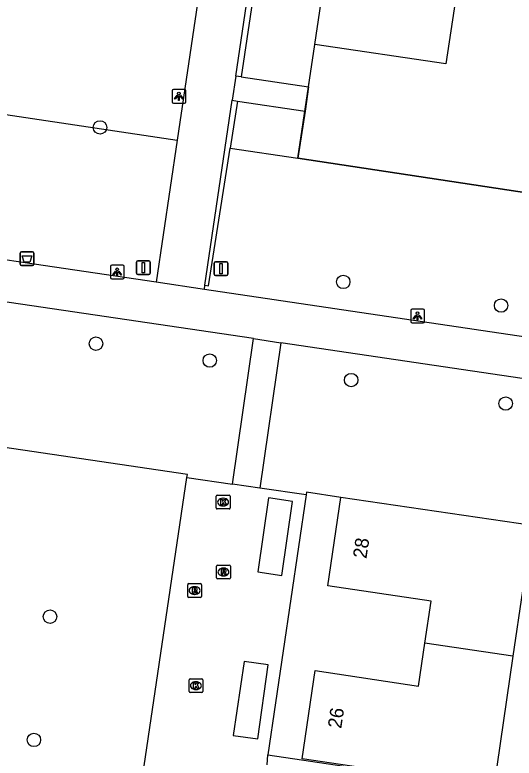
# Model space of a CAD drawing. Extents: x 164150 to 165261, y 382513 to 383432.
# Drawn here: x 164477.9 to 164514.2, y 382999.8 to 383053.9 of the extents above; entities that cross this region are included whole.
import ezdxf

# ---------------------------------------------------------------- set-up
doc = ezdxf.new("R2010")
doc.units = 0
for name, color, linetype in [('IMGEO_Afvalbak', 7, 'Continuous'), ('IMGEO_Boom', 7, 'Continuous'), ('IMGEO_Fietspad_gesloten', 7, 'Continuous'), ('IMGEO_Groenvoorziening', 7, 'Continuous'), ('IMGEO_Haag', 7, 'Continuous'), ('IMGEO_Hek', 7, 'Continuous'), ('IMGEO_Kolk', 7, 'Continuous'), ('IMGEO_Lichtpunt', 7, 'Continuous'), ('IMGEO_Pand', 7, 'Continuous'), ('IMGEO_Pand_nummerreeks', 7, 'Continuous'), ('IMGEO_Rijbaan_lokaal_open', 7, 'Continuous'), ('IMGEO_Rioolput', 7, 'Continuous'), ('IMGEO_Verkeersbordpaal', 7, 'Continuous'), ('IMGEO_Voetpad_gesloten', 7, 'Continuous'), ('IMGEO_Voetpad_halfverhard', 7, 'Continuous'), ('IMGEO_Voetpad_open', 7, 'Continuous')]:
    doc.layers.add(name, color=color, linetype=linetype)

msp = doc.modelspace()

# ---------------------------------------------------------------- linework, layer by layer
at = {"layer": 'IMGEO_Afvalbak'}
for p, q in [((164478.364, 383036.636), (164479.154, 383036.636)), ((164479.154, 383036.636), (164478.364, 383036.636)), ((164478.264, 383035.736), (164478.264, 383036.536)), ((164478.264, 383036.536), (164478.264, 383035.736)), ((164479.254, 383036.536), (164479.254, 383035.736)), ((164479.254, 383035.736), (164479.254, 383036.536)), ((164479.154, 383035.636), (164478.364, 383035.636)), ((164478.364, 383035.636), (164479.154, 383035.636))]:
    msp.add_line(p, q, dxfattribs=at)
msp.add_lwpolyline([(164478.407, 383036.35), (164479.111, 383036.35), (164478.962, 383035.88), (164478.556, 383035.88), (164478.407, 383036.35)], dxfattribs=at)
for centre, start, end in [((164478.364, 383036.536), 90, 180), ((164478.364, 383036.536), 90, 180), ((164479.154, 383036.536), 0, 90), ((164479.154, 383036.536), 360, 90), ((164478.364, 383035.736), 180, 270), ((164478.364, 383035.736), 180, 270), ((164479.154, 383035.736), 270, 0), ((164479.154, 383035.736), 270, 0)]:
    msp.add_arc(centre, 0.1, start, end, dxfattribs=at)
at = {"layer": 'IMGEO_Boom'}
for centre in [(164484.075, 383045.692), (164501.769, 383034.443), (164513.25, 383032.723), (164483.78, 383029.945), (164492.055, 383028.719), (164502.343, 383027.299), (164513.585, 383025.587), (164480.437, 383010.074), (164479.266, 383001.1)]:
    msp.add_circle(centre, 0.489, dxfattribs=at)
at = {"layer": 'IMGEO_Fietspad_gesloten'}
for points in [[(164488.159, 383034.419), (164477.812, 383035.957), (164476.86, 383036.098), (164470.165, 383037.076)], [(164495.251, 383030.312), (164475.967, 383033.169), (164468.317, 383034.298)], [(164491.665, 383033.898), (164488.159, 383034.419)], [(164540.385, 383026.655), (164491.665, 383033.898)], [(164493.71, 383019.713), (164495.251, 383030.312)], [(164495.251, 383030.312), (164497.229, 383030.019)], [(164497.229, 383030.019), (164495.689, 383019.425)], [(164557.267, 383021.125), (164497.229, 383030.019)]]:
    msp.add_lwpolyline(points, dxfattribs=at)
at = {"layer": 'IMGEO_Groenvoorziening'}
for points in [[(164499.25, 383048.639), (164499.711, 383051.727)], [(164471.706, 383047.448), (164489.692, 383044.763)], [(164498.987, 383046.877), (164498.474, 383043.442)], [(164493.537, 383044.188), (164498.474, 383043.442)], [(164498.474, 383043.442), (164537.669, 383037.513), (164537.713, 383037.811)], [(164490.395, 383020.195), (164490.427, 383020.412), (164473.524, 383022.914)], [(164501.59, 383018.76), (164499.092, 383019.13), (164499.063, 383018.935)]]:
    msp.add_lwpolyline(points, dxfattribs=at)
at = {"layer": 'IMGEO_Haag'}
for points in [[(164497.85, 383072.978), (164494.335, 383049.373)], [(164494.073, 383047.611), (164493.537, 383044.188)], [(164491.71, 383034.202), (164491.967, 383034.165), (164493.537, 383044.188)]]:
    msp.add_lwpolyline(points, dxfattribs=at)
at = {"layer": 'IMGEO_Hek'}
for points in [[(164498.474, 383043.442), (164499.711, 383051.727)], [(164537.713, 383037.811), (164537.669, 383037.513), (164498.474, 383043.442)]]:
    msp.add_lwpolyline(points, dxfattribs=at)
at = {"layer": 'IMGEO_Kolk'}
for p, q in [((164492.531, 383017.986), (164492.531, 383018.838)), ((164492.606, 383018.912), (164493.458, 383018.912)), ((164493.532, 383018.838), (164493.532, 383017.986)), ((164493.019, 383018.692), (164493.044, 383018.692)), ((164493.458, 383017.912), (164492.606, 383017.912)), ((164493.042, 383018.132), (164493.017, 383018.132)), ((164490.552, 383004.625), (164490.552, 383005.477)), ((164490.627, 383005.551), (164491.479, 383005.551)), ((164491.04, 383005.331), (164491.065, 383005.331)), ((164491.553, 383005.477), (164491.553, 383004.625)), ((164491.063, 383004.771), (164491.038, 383004.771)), ((164491.479, 383004.551), (164490.627, 383004.551))]:
    msp.add_line(p, q, dxfattribs=at)
for points in [[(164492.531, 383017.986), (164492.531, 383018.838)], [(164492.606, 383018.912), (164493.458, 383018.912)], [(164493.532, 383018.838), (164493.532, 383017.986)], [(164492.852, 383018.612), (164492.975, 383018.612), (164492.975, 383018.461), (164493.105, 383018.612), (164493.269, 383018.612), (164493.123, 383018.461), (164493.276, 383018.212), (164493.124, 383018.212), (164493.039, 383018.376), (164492.975, 383018.309), (164492.975, 383018.212), (164492.852, 383018.212), (164492.852, 383018.612)], [(164493.458, 383017.912), (164492.606, 383017.912)], [(164490.552, 383004.625), (164490.552, 383005.477)], [(164490.627, 383005.551), (164491.479, 383005.551)], [(164490.873, 383005.251), (164490.996, 383005.251), (164490.996, 383005.1), (164491.126, 383005.251), (164491.29, 383005.251), (164491.144, 383005.1), (164491.297, 383004.851), (164491.145, 383004.851), (164491.06, 383005.015), (164490.996, 383004.948), (164490.996, 383004.851), (164490.873, 383004.851), (164490.873, 383005.251)], [(164491.553, 383005.477), (164491.553, 383004.625)], [(164491.479, 383004.551), (164490.627, 383004.551)]]:
    msp.add_lwpolyline(points, dxfattribs=at)
for centre, start, end in [((164492.608, 383018.836), 91.552, 178.448), ((164492.608, 383018.836), 91.552, 178.448), ((164493.456, 383018.836), 1.552, 88.448), ((164493.456, 383018.836), 1.552, 88.448), ((164492.608, 383017.988), 181.552, 268.448), ((164492.608, 383017.988), 181.552, 268.448), ((164493.456, 383017.988), 271.552, 358.448), ((164493.456, 383017.988), 271.552, 358.448), ((164490.629, 383005.475), 91.552, 178.448), ((164490.629, 383005.475), 91.552, 178.448), ((164491.477, 383005.475), 1.552, 88.448), ((164491.477, 383005.475), 1.552, 88.448), ((164490.629, 383004.627), 181.552, 268.448), ((164490.629, 383004.627), 181.552, 268.448), ((164491.477, 383004.627), 271.552, 358.448), ((164491.477, 383004.627), 271.552, 358.448)]:
    msp.add_arc(centre, 0.0765, start, end, dxfattribs=at)
for centre, major_axis, ratio, start_param, end_param in [((164493.018, 383018.412), (-0.387, 0.002), 0.722429, 4.712389, 7.853982), ((164493.043, 383018.412), (-0.39, 0.002), 0.717154, 1.570796, 4.712389), ((164491.039, 383005.051), (-0.387, 0.002), 0.722429, 4.712389, 7.853982), ((164491.064, 383005.051), (-0.39, 0.002), 0.717154, 1.570796, 4.712389)]:
    msp.add_ellipse(centre, major_axis=major_axis, ratio=ratio, start_param=start_param, end_param=end_param, dxfattribs=at)
at = {"layer": 'IMGEO_Lichtpunt'}
for p, q in [((164489.315, 383048.366), (164489.315, 383047.559)), ((164489.315, 383048.366), (164489.315, 383047.559)), ((164490.217, 383048.461), (164489.409, 383048.461)), ((164490.217, 383048.461), (164489.409, 383048.461)), ((164490.311, 383047.559), (164490.311, 383048.366)), ((164490.311, 383047.559), (164490.311, 383048.366)), ((164489.409, 383047.465), (164490.217, 383047.465)), ((164489.409, 383047.465), (164490.217, 383047.465)), ((164484.83, 383035.561), (164484.83, 383034.754)), ((164484.83, 383035.561), (164484.83, 383034.754)), ((164485.732, 383035.656), (164484.924, 383035.656)), ((164485.732, 383035.656), (164484.924, 383035.656)), ((164485.826, 383034.754), (164485.826, 383035.561)), ((164485.826, 383034.754), (164485.826, 383035.561)), ((164484.924, 383034.66), (164485.732, 383034.66)), ((164484.924, 383034.66), (164485.732, 383034.66)), ((164506.678, 383032.364), (164506.678, 383031.557)), ((164506.678, 383032.364), (164506.678, 383031.557)), ((164507.58, 383032.459), (164506.772, 383032.459)), ((164507.58, 383032.459), (164506.772, 383032.459)), ((164507.674, 383031.557), (164507.674, 383032.364)), ((164507.674, 383031.557), (164507.674, 383032.364)), ((164506.772, 383031.463), (164507.58, 383031.463)), ((164506.772, 383031.463), (164507.58, 383031.463))]:
    msp.add_line(p, q, dxfattribs=at)
for points in [[(164489.689, 383048.03), (164489.728, 383048.002), (164489.54, 383047.74), (164489.502, 383047.767), (164489.689, 383048.03)], [(164489.791, 383047.982), (164489.838, 383047.982), (164489.838, 383047.66), (164489.791, 383047.66), (164489.791, 383047.982)], [(164489.901, 383048.002), (164489.939, 383048.029), (164490.126, 383047.767), (164490.087, 383047.739), (164489.901, 383048.002)], [(164485.204, 383035.225), (164485.243, 383035.197), (164485.055, 383034.935), (164485.017, 383034.962), (164485.204, 383035.225)], [(164485.306, 383035.177), (164485.353, 383035.177), (164485.353, 383034.855), (164485.306, 383034.855), (164485.306, 383035.177)], [(164485.416, 383035.197), (164485.454, 383035.224), (164485.641, 383034.962), (164485.602, 383034.934), (164485.416, 383035.197)], [(164507.052, 383032.028), (164507.091, 383032), (164506.903, 383031.738), (164506.865, 383031.765), (164507.052, 383032.028)], [(164507.154, 383031.98), (164507.201, 383031.98), (164507.201, 383031.658), (164507.154, 383031.658), (164507.154, 383031.98)], [(164507.264, 383032), (164507.302, 383032.027), (164507.489, 383031.765), (164507.45, 383031.737), (164507.264, 383032)]]:
    msp.add_lwpolyline(points, dxfattribs=at)
for centre in [(164489.814, 383048.164), (164485.329, 383035.359), (164507.177, 383032.162)]:
    msp.add_circle(centre, 0.0994, dxfattribs=at)
for centre, start, end in [((164489.409, 383048.366), 90, 180), ((164489.409, 383048.366), 90, 180), ((164490.217, 383048.366), 0, 90), ((164490.217, 383048.366), 0, 90), ((164489.409, 383047.559), 180, 270), ((164489.409, 383047.559), 180, 270), ((164490.217, 383047.559), 270, 0), ((164490.217, 383047.559), 270, 360), ((164484.924, 383035.561), 90, 180), ((164484.924, 383035.561), 90, 180), ((164485.732, 383035.561), 0, 90), ((164485.732, 383035.561), 0, 90), ((164484.924, 383034.754), 180, 270), ((164484.924, 383034.754), 180, 270), ((164485.732, 383034.754), 270, 0), ((164485.732, 383034.754), 270, 360), ((164506.772, 383032.364), 90, 180), ((164506.772, 383032.364), 90, 180), ((164507.58, 383032.364), 0, 90), ((164507.58, 383032.364), 0, 90), ((164506.772, 383031.557), 180, 270), ((164506.772, 383031.557), 180, 270), ((164507.58, 383031.557), 270, 0), ((164507.58, 383031.557), 270, 360)]:
    msp.add_arc(centre, 0.0946, start, end, dxfattribs=at)
at = {"layer": 'IMGEO_Pand'}
for points in [[(164499.711, 383051.727), (164500.898, 383059.768)], [(164510.434, 383058.359), (164509.235, 383050.319), (164499.711, 383051.727)], [(164507.703, 383008.132), (164508.161, 383011.199), (164500.641, 383012.312), (164501.59, 383018.76)], [(164515.519, 383016.715), (164501.59, 383018.76)], [(164515.519, 383016.715), (164514.115, 383007.187)], [(164514.115, 383007.187), (164512.711, 382997.659), (164498.772, 382999.727), (164499.73, 383006.146), (164507.24, 383005.025), (164507.703, 383008.132)], [(164514.115, 383007.187), (164507.703, 383008.132)]]:
    msp.add_lwpolyline(points, dxfattribs=at)
at = {"layer": 'IMGEO_Rijbaan_lokaal_open'}
for points in [[(164486.551, 382993.124), (164486.385, 382993.149), (164490.395, 383020.195)], [(164490.395, 383020.195), (164493.71, 383019.713)], [(164495.689, 383019.425), (164493.71, 383019.713)], [(164499.063, 383018.935), (164495.689, 383019.425)], [(164499.063, 383018.935), (164496.276, 383000.022)], [(164497.294, 383013.061), (164498.073, 383018.463), (164496.335, 383018.717), (164495.543, 383013.341), (164497.294, 383013.061)], [(164495.546, 383001.168), (164496.306, 383006.561), (164494.565, 383006.812), (164493.769, 383001.425), (164495.546, 383001.168)], [(164496.241, 382999.283), (164496.276, 383000.022)]]:
    msp.add_lwpolyline(points, dxfattribs=at)
at = {"layer": 'IMGEO_Rioolput'}
for p, q in [((164492.554, 383012.898), (164492.554, 383013.75)), ((164492.629, 383013.824), (164493.481, 383013.824)), ((164493.042, 383013.604), (164493.067, 383013.604)), ((164493.555, 383013.75), (164493.555, 383012.898)), ((164493.481, 383012.824), (164492.629, 383012.824)), ((164493.065, 383013.044), (164493.04, 383013.044)), ((164490.451, 383011.55), (164490.451, 383012.402)), ((164490.526, 383012.476), (164491.378, 383012.476)), ((164490.939, 383012.256), (164490.964, 383012.256)), ((164491.452, 383012.402), (164491.452, 383011.55)), ((164491.378, 383011.476), (164490.526, 383011.476)), ((164490.962, 383011.696), (164490.937, 383011.696))]:
    msp.add_line(p, q, dxfattribs=at)
for points in [[(164492.554, 383012.898), (164492.554, 383013.75)], [(164492.629, 383013.824), (164493.481, 383013.824)], [(164493.143, 383013.522), (164492.891, 383013.524), (164492.891, 383013.124)], [(164493.069, 383013.443), (164493.015, 383013.443), (164493.015, 383013.362)], [(164493.015, 383013.362), (164493.067, 383013.362)], [(164493.555, 383013.75), (164493.555, 383012.898)], [(164493.481, 383012.824), (164492.629, 383012.824)], [(164492.891, 383013.124), (164493.015, 383013.124), (164493.015, 383013.286), (164493.026, 383013.286)], [(164493.073, 383013.257), (164493.144, 383013.124), (164493.284, 383013.124), (164493.219, 383013.25)], [(164490.451, 383011.55), (164490.451, 383012.402)], [(164490.526, 383012.476), (164491.378, 383012.476)], [(164491.452, 383012.402), (164491.452, 383011.55)], [(164491.04, 383012.174), (164490.788, 383012.176), (164490.788, 383011.776)], [(164490.788, 383011.776), (164490.912, 383011.776), (164490.912, 383011.938), (164490.923, 383011.938)], [(164490.966, 383012.095), (164490.912, 383012.095), (164490.912, 383012.014)], [(164490.912, 383012.014), (164490.964, 383012.014)], [(164490.97, 383011.909), (164491.041, 383011.776), (164491.181, 383011.776), (164491.116, 383011.902)], [(164491.378, 383011.476), (164490.526, 383011.476)]]:
    msp.add_lwpolyline(points, dxfattribs=at)
for centre, radius, start, end in [((164492.631, 383013.748), 0.0765, 91.552, 178.448), ((164492.631, 383013.748), 0.0765, 91.552, 178.448), ((164493.051, 383013.551), 0.19, 274.7715, 282.9687), ((164493.075, 383013.347), 0.0964, 77.0061, 93.1865), ((164493.089, 383013.404), 0.0378, 276.6634, 79.6772), ((164493.142, 383013.412), 0.109, 350.3612, 89.416), ((164493.14, 383013.412), 0.112, 277.5842, 350.9817), ((164493.479, 383013.748), 0.0765, 1.552, 88.448), ((164493.479, 383013.748), 0.0765, 1.552, 88.448), ((164492.631, 383012.9), 0.0765, 181.552, 268.448), ((164492.631, 383012.9), 0.0765, 181.552, 268.448), ((164493.025, 383013.233), 0.0533, 26.0293, 88.6989), ((164493.124, 383013.197), 0.108, 29.5134, 73.7905), ((164493.479, 383012.9), 0.0765, 271.552, 358.448), ((164493.479, 383012.9), 0.0765, 271.552, 358.448), ((164490.528, 383012.4), 0.0765, 91.552, 178.448), ((164490.528, 383012.4), 0.0765, 91.552, 178.448), ((164491.376, 383012.4), 0.0765, 1.552, 88.448), ((164491.376, 383012.4), 0.0765, 1.552, 88.448), ((164490.922, 383011.885), 0.0533, 26.0293, 88.6989), ((164490.948, 383012.203), 0.19, 274.7715, 282.9687), ((164490.972, 383011.999), 0.0964, 77.0061, 93.1865), ((164490.986, 383012.056), 0.0378, 276.6634, 79.6772), ((164491.039, 383012.064), 0.109, 350.3612, 89.416), ((164491.037, 383012.064), 0.112, 277.5842, 350.9817), ((164491.021, 383011.849), 0.108, 29.5134, 73.7905), ((164490.528, 383011.552), 0.0765, 181.552, 268.448), ((164490.528, 383011.552), 0.0765, 181.552, 268.448), ((164491.376, 383011.552), 0.0765, 271.552, 358.448), ((164491.376, 383011.552), 0.0765, 271.552, 358.448)]:
    msp.add_arc(centre, radius, start, end, dxfattribs=at)
for centre, major_axis, ratio, start_param, end_param in [((164493.041, 383013.324), (-0.387, 0.002), 0.722429, 4.712389, 7.853982), ((164493.066, 383013.324), (-0.39, 0.002), 0.717154, 1.570796, 4.712389), ((164490.938, 383011.976), (-0.387, 0.002), 0.722429, 4.712389, 7.853982), ((164490.963, 383011.976), (-0.39, 0.002), 0.717154, 1.570796, 4.712389)]:
    msp.add_ellipse(centre, major_axis=major_axis, ratio=ratio, start_param=start_param, end_param=end_param, dxfattribs=at)
at = {"layer": 'IMGEO_Verkeersbordpaal'}
for p, q in [((164486.729, 383035.072), (164486.729, 383035.872)), ((164486.729, 383035.872), (164486.729, 383035.072)), ((164486.829, 383035.972), (164487.619, 383035.972)), ((164487.619, 383035.972), (164486.829, 383035.972)), ((164487.719, 383035.872), (164487.719, 383035.072)), ((164487.719, 383035.072), (164487.719, 383035.872)), ((164492.381, 383035.002), (164492.381, 383035.802)), ((164492.381, 383035.802), (164492.381, 383035.002)), ((164492.481, 383035.902), (164493.271, 383035.902)), ((164493.271, 383035.902), (164492.481, 383035.902)), ((164493.371, 383035.802), (164493.371, 383035.002)), ((164493.371, 383035.002), (164493.371, 383035.802)), ((164487.619, 383034.972), (164486.829, 383034.972)), ((164486.829, 383034.972), (164487.619, 383034.972)), ((164493.271, 383034.902), (164492.481, 383034.902)), ((164492.481, 383034.902), (164493.271, 383034.902))]:
    msp.add_line(p, q, dxfattribs=at)
for points in [[(164487.149, 383035.847), (164487.299, 383035.847), (164487.299, 383035.097), (164487.149, 383035.097), (164487.149, 383035.847)], [(164492.801, 383035.777), (164492.951, 383035.777), (164492.951, 383035.027), (164492.801, 383035.027), (164492.801, 383035.777)]]:
    msp.add_lwpolyline(points, dxfattribs=at)
for centre, start, end in [((164486.829, 383035.872), 90, 180), ((164486.829, 383035.872), 90, 180), ((164487.619, 383035.872), 0, 90), ((164487.619, 383035.872), 360, 90), ((164492.481, 383035.802), 90, 180), ((164492.481, 383035.802), 90, 180), ((164493.271, 383035.802), 0, 90), ((164493.271, 383035.802), 360, 90), ((164486.829, 383035.072), 180, 270), ((164486.829, 383035.072), 180, 270), ((164487.619, 383035.072), 270, 0), ((164487.619, 383035.072), 270, 0), ((164492.481, 383035.002), 180, 270), ((164492.481, 383035.002), 180, 270), ((164493.271, 383035.002), 270, 0), ((164493.271, 383035.002), 270, 0)]:
    msp.add_arc(centre, 0.1, start, end, dxfattribs=at)
at = {"layer": 'IMGEO_Voetpad_gesloten'}
for points in [[(164500.185, 383130.675), (164502.37, 383130.298), (164489.692, 383044.763)], [(164493.959, 383049.428), (164497.447, 383073.037)], [(164493.959, 383049.428), (164493.699, 383047.666)], [(164491.71, 383034.202), (164493.699, 383047.666)], [(164489.692, 383044.763), (164488.159, 383034.419)], [(164491.665, 383033.898), (164491.71, 383034.202)]]:
    msp.add_lwpolyline(points, dxfattribs=at)
at = {"layer": 'IMGEO_Voetpad_halfverhard'}
for points in [[(164494.335, 383049.373), (164493.959, 383049.428)], [(164494.335, 383049.373), (164499.25, 383048.639)], [(164499.25, 383048.639), (164498.987, 383046.877)], [(164493.699, 383047.666), (164494.073, 383047.611)], [(164494.073, 383047.611), (164498.987, 383046.877)]]:
    msp.add_lwpolyline(points, dxfattribs=at)
at = {"layer": 'IMGEO_Voetpad_open'}
msp.add_lwpolyline([(164496.276, 383000.022), (164545.95, 382992.647), (164548.758, 383011.551)], dxfattribs=at)

# ---------------------------------------------------------------- texts
at = {"layer": 'IMGEO_Pand_nummerreeks'}
for s, rotation, p in [('28', 81.6293, (164503.454, 383014.261)), ('26', 81.509, (164501.622, 383001.892))]:
    msp.add_text(s, height=1, rotation=rotation, dxfattribs=at).set_placement(p)

doc.saveas('drawing.dxf')
